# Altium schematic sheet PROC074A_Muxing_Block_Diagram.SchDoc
size 431 x 279 mm; Date: Not shown in title block; ApprovedBy: Not shown in title block; CheckedBy: Not shown in title block; Author: Not shown in title block; CompanyName: Not shown in title block; Engineer: Not shown in title block; Organization: Not shown in title block; Address1: Not shown in title block; Address2: Not shown in title block; Address3: Not shown in title block; Address4: Not shown in title block; DocumentNumber: 1; Revision: Use project parameter SCH_Rev; SheetNumber: 3; SheetTotal: 22; PageSetup: Record=PageOptions¦CenterHorizontal=True¦CenterVertical=True¦PrintScale=1.00¦XCorrection=1.00¦YCorrection=1.00¦PrintKind=0¦BorderSize=5000000¦LeftOffset=0¦BottomOffset=0¦Orientation=2¦PaperLength=1000¦PaperWidth=1000¦Scale=100¦PaperSource=15¦PrintQuality=600¦MediaType=1¦DitherType=10¦PaperKind=Letter¦PrintScaleMode=1
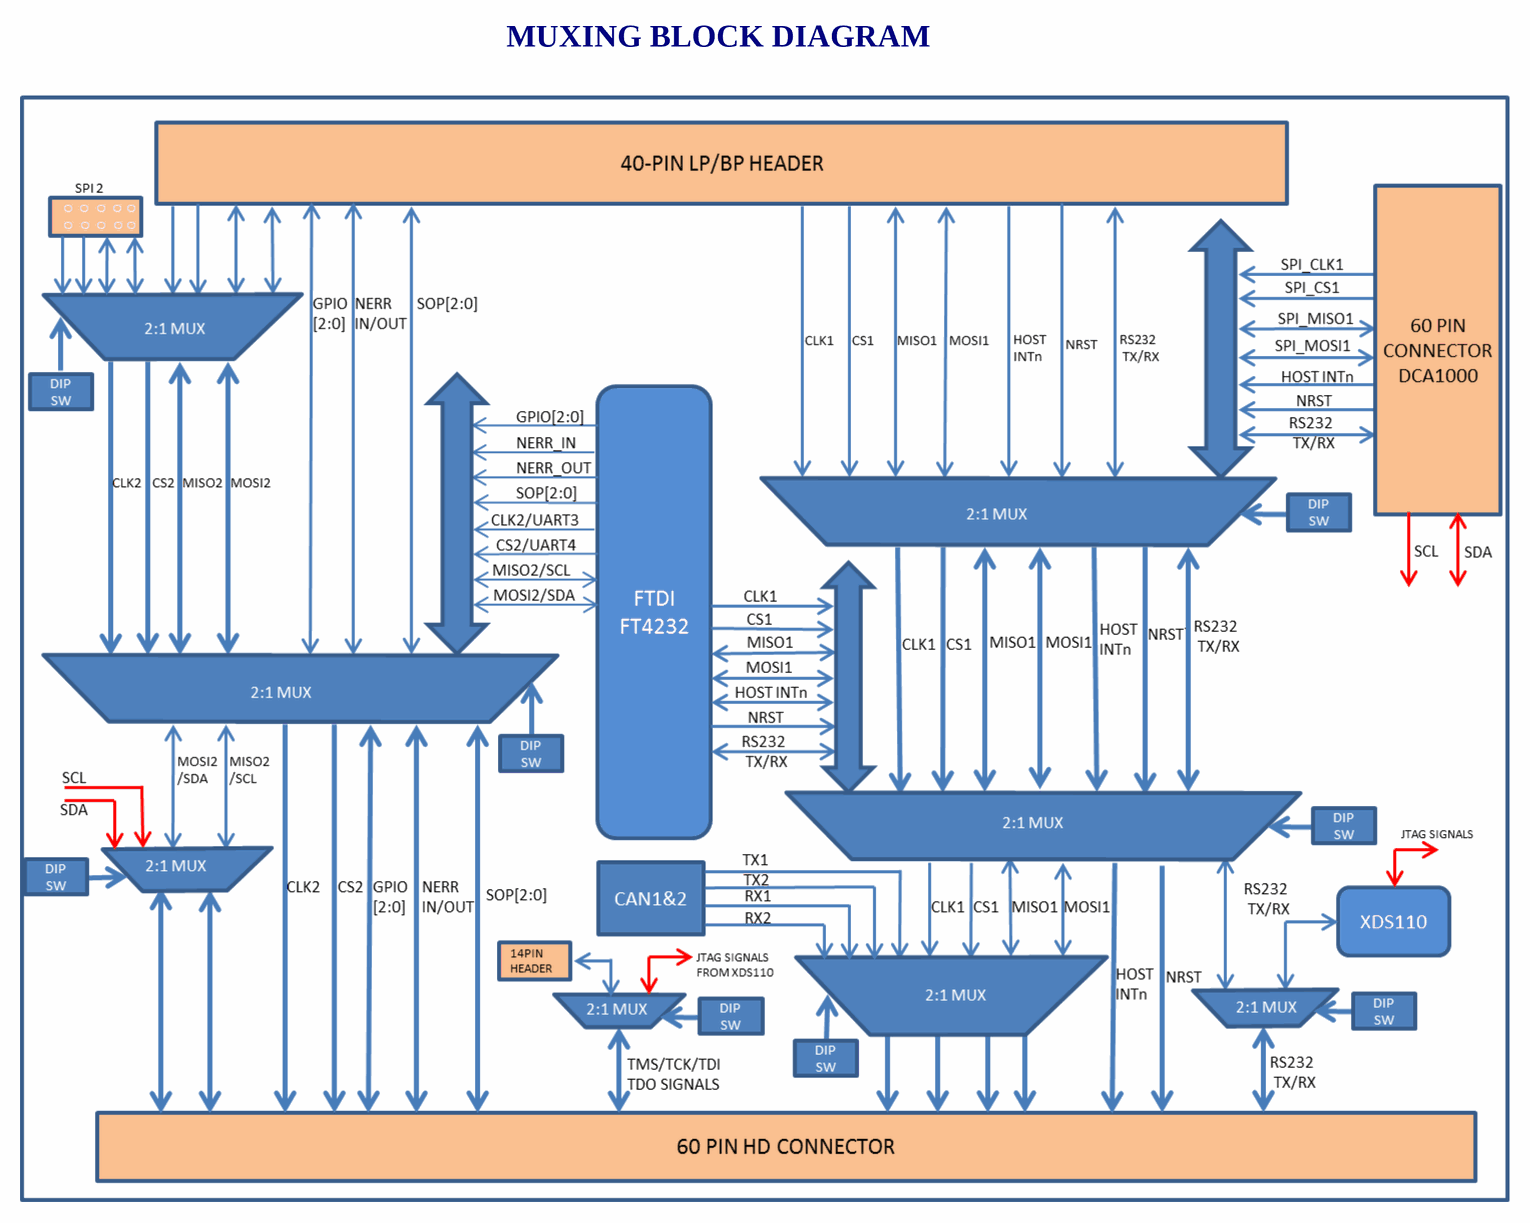
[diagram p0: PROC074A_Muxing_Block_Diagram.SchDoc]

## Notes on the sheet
- MUXING BLOCK DIAGRAM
